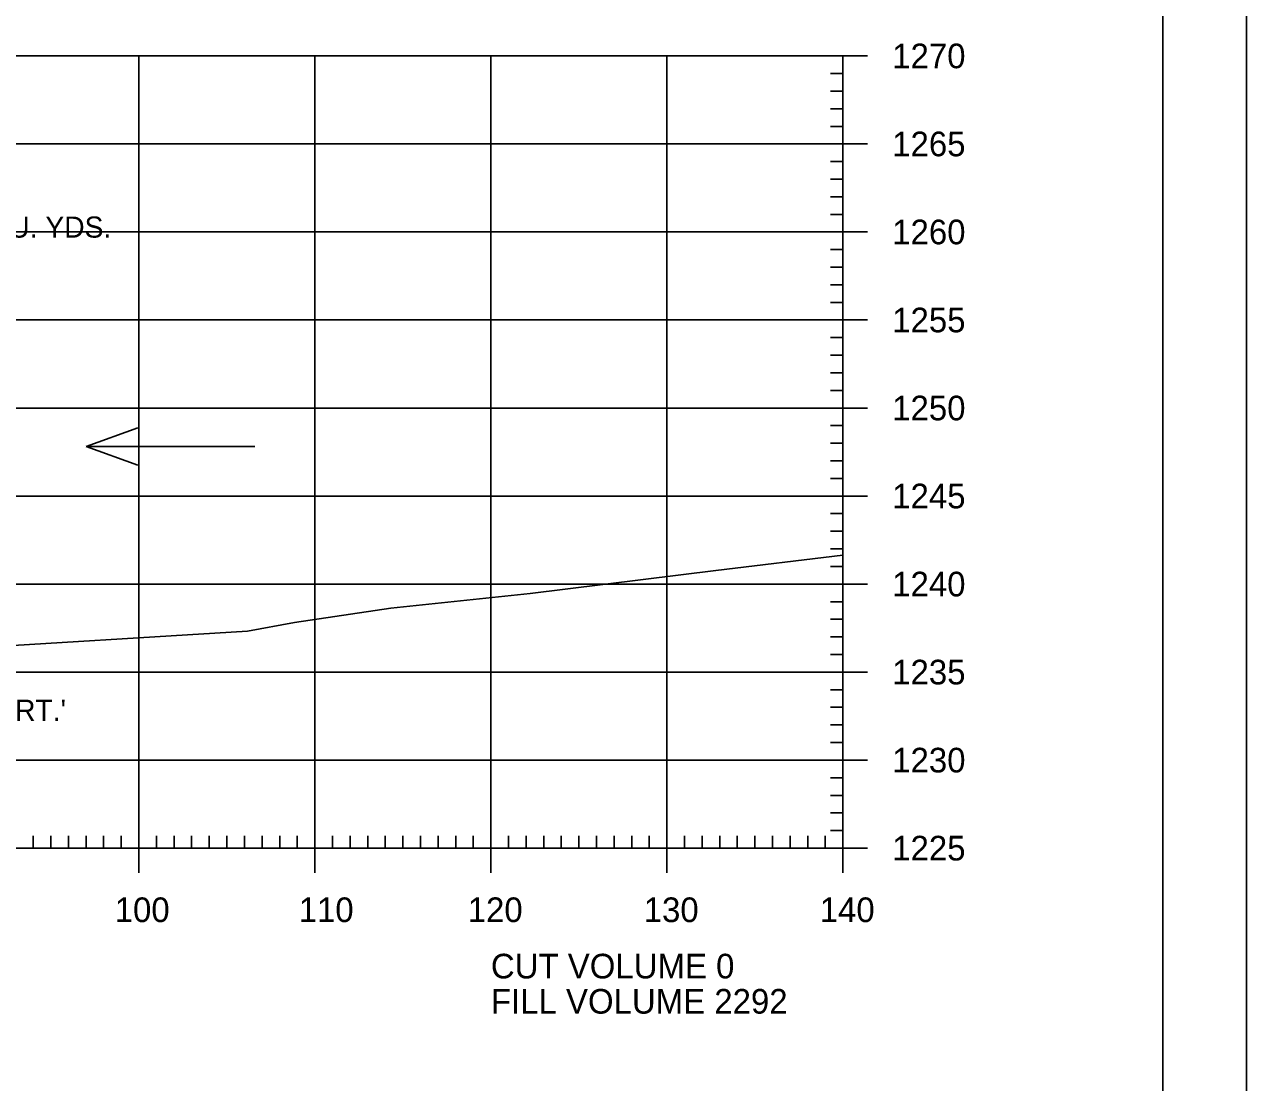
# Model space of a CAD drawing. Extents: x 1406028 to 1412453, y 321733 to 325986.
# Drawn here: x 1409148.3 to 1409217.7, y 321949.6 to 322009.7 of the extents above; entities that cross this region are included whole.
import ezdxf

# ---------------------------------------------------------------- set-up
doc = ezdxf.new("R2010")
doc.units = 0
for name, color, linetype in [('R_Axis', 7, 'Continuous'), ('R_Axis Annot', 7, 'Continuous'), ('R_Border', 7, 'Continuous'), ('R_Draft', 7, 'Continuous'), ('R_Exist Surface', 7, 'Continuous'), ('R_Grid', 7, 'Continuous'), ('R_Horz Alg Annot', 7, 'Continuous'), ('R_No Plot', 7, 'Continuous'), ('R_Water Annot', 7, 'Continuous')]:
    doc.layers.add(name, color=color, linetype=linetype)

msp = doc.modelspace()

# ---------------------------------------------------------------- linework, layer by layer
at = {"layer": 'R_Axis'}
for p, q in [((1409196.215, 322007.877), (1409193.415, 322007.877)), ((1409194.815, 321962.877), (1409194.815, 322007.877)), ((1409194.815, 322006.877), (1409194.115, 322006.877)), ((1409194.815, 322005.877), (1409194.115, 322005.877)), ((1409194.815, 322004.877), (1409194.115, 322004.877)), ((1409194.815, 322003.877), (1409194.115, 322003.877)), ((1409196.215, 322002.877), (1409193.415, 322002.877)), ((1409194.815, 322001.877), (1409194.115, 322001.877)), ((1409194.815, 322000.877), (1409194.115, 322000.877)), ((1409194.815, 321999.877), (1409194.115, 321999.877)), ((1409194.815, 321998.877), (1409194.115, 321998.877)), ((1409196.215, 321997.877), (1409193.415, 321997.877)), ((1409194.815, 321996.877), (1409194.115, 321996.877)), ((1409194.815, 321995.877), (1409194.115, 321995.877)), ((1409194.815, 321994.877), (1409194.115, 321994.877)), ((1409194.815, 321993.877), (1409194.115, 321993.877)), ((1409196.215, 321992.877), (1409193.415, 321992.877)), ((1409194.815, 321991.877), (1409194.115, 321991.877)), ((1409194.815, 321990.877), (1409194.115, 321990.877)), ((1409194.815, 321989.877), (1409194.115, 321989.877)), ((1409194.815, 321988.877), (1409194.115, 321988.877)), ((1409196.215, 321987.877), (1409193.415, 321987.877)), ((1409194.815, 321986.877), (1409194.115, 321986.877)), ((1409194.815, 321985.877), (1409194.115, 321985.877)), ((1409194.815, 321984.877), (1409194.115, 321984.877)), ((1409194.815, 321983.877), (1409194.115, 321983.877)), ((1409196.215, 321982.877), (1409193.415, 321982.877)), ((1409194.815, 321981.877), (1409194.115, 321981.877)), ((1409194.815, 321980.877), (1409194.115, 321980.877)), ((1409194.815, 321979.877), (1409194.115, 321979.877)), ((1409194.815, 321978.877), (1409194.115, 321978.877)), ((1409196.215, 321977.877), (1409193.415, 321977.877)), ((1409194.815, 321976.877), (1409194.115, 321976.877)), ((1409194.815, 321975.877), (1409194.115, 321975.877)), ((1409194.815, 321974.877), (1409194.115, 321974.877)), ((1409194.815, 321973.877), (1409194.115, 321973.877)), ((1409196.215, 321972.877), (1409193.415, 321972.877)), ((1409194.815, 321971.877), (1409194.115, 321971.877)), ((1409194.815, 321970.877), (1409194.115, 321970.877)), ((1409194.815, 321969.877), (1409194.115, 321969.877)), ((1409194.815, 321968.877), (1409194.115, 321968.877)), ((1409196.215, 321967.877), (1409193.415, 321967.877)), ((1409194.815, 321966.877), (1409194.115, 321966.877)), ((1409194.815, 321965.877), (1409194.115, 321965.877)), ((1409194.815, 321964.877), (1409194.115, 321964.877)), ((1409154.815, 321961.477), (1409154.815, 321964.277)), ((1409164.815, 321961.477), (1409164.815, 321964.277)), ((1409174.815, 321961.477), (1409174.815, 321964.277)), ((1409184.815, 321961.477), (1409184.815, 321964.277)), ((1409194.815, 321961.477), (1409194.815, 321964.277)), ((1409148.815, 321962.877), (1409148.815, 321963.577)), ((1409149.815, 321962.877), (1409149.815, 321963.577)), ((1409150.815, 321962.877), (1409150.815, 321963.577)), ((1409151.815, 321962.877), (1409151.815, 321963.577)), ((1409152.815, 321962.877), (1409152.815, 321963.577)), ((1409153.815, 321962.877), (1409153.815, 321963.577)), ((1409155.815, 321962.877), (1409155.815, 321963.577)), ((1409156.815, 321962.877), (1409156.815, 321963.577)), ((1409157.815, 321962.877), (1409157.815, 321963.577)), ((1409158.815, 321962.877), (1409158.815, 321963.577)), ((1409159.815, 321962.877), (1409159.815, 321963.577)), ((1409160.815, 321962.877), (1409160.815, 321963.577)), ((1409161.815, 321962.877), (1409161.815, 321963.577)), ((1409162.815, 321962.877), (1409162.815, 321963.577)), ((1409163.815, 321962.877), (1409163.815, 321963.577)), ((1409165.815, 321962.877), (1409165.815, 321963.577)), ((1409166.815, 321962.877), (1409166.815, 321963.577)), ((1409167.815, 321962.877), (1409167.815, 321963.577)), ((1409168.815, 321962.877), (1409168.815, 321963.577)), ((1409169.815, 321962.877), (1409169.815, 321963.577)), ((1409170.815, 321962.877), (1409170.815, 321963.577)), ((1409171.815, 321962.877), (1409171.815, 321963.577)), ((1409172.815, 321962.877), (1409172.815, 321963.577)), ((1409173.815, 321962.877), (1409173.815, 321963.577)), ((1409175.815, 321962.877), (1409175.815, 321963.577)), ((1409176.815, 321962.877), (1409176.815, 321963.577)), ((1409177.815, 321962.877), (1409177.815, 321963.577)), ((1409178.815, 321962.877), (1409178.815, 321963.577)), ((1409179.815, 321962.877), (1409179.815, 321963.577)), ((1409180.815, 321962.877), (1409180.815, 321963.577)), ((1409181.815, 321962.877), (1409181.815, 321963.577)), ((1409182.815, 321962.877), (1409182.815, 321963.577)), ((1409183.815, 321962.877), (1409183.815, 321963.577)), ((1409185.815, 321962.877), (1409185.815, 321963.577)), ((1409186.815, 321962.877), (1409186.815, 321963.577)), ((1409187.815, 321962.877), (1409187.815, 321963.577)), ((1409188.815, 321962.877), (1409188.815, 321963.577)), ((1409189.815, 321962.877), (1409189.815, 321963.577)), ((1409190.815, 321962.877), (1409190.815, 321963.577)), ((1409191.815, 321962.877), (1409191.815, 321963.577)), ((1409192.815, 321962.877), (1409192.815, 321963.577)), ((1409193.815, 321962.877), (1409193.815, 321963.577)), ((1409194.815, 321963.877), (1409194.115, 321963.877)), ((1408914.815, 321962.877), (1409194.815, 321962.877)), ((1409196.215, 321962.877), (1409193.415, 321962.877))]:
    msp.add_line(p, q, dxfattribs=at)
at = {"layer": 'R_Border'}
msp.add_line((1409212.995, 321846.877), (1409212.995, 322052.337), dxfattribs=at)
at = {"layer": 'R_Exist Surface'}
msp.add_lwpolyline([(1409073.222, 321972.485), (1409082.091, 321972.369), (1409092.828, 321972.247), (1409093.041, 321972.223), (1409098.394, 321971.718), (1409106.967, 321970.902), (1409107.271, 321970.881), (1409107.501, 321970.857), (1409121.823, 321972.904), (1409122.285, 321972.953), (1409133.015, 321973.452), (1409137.681, 321973.788), (1409144.241, 321974.185), (1409160.985, 321975.208), (1409163.653, 321975.692), (1409169.134, 321976.513), (1409177.046, 321977.346), (1409187.589, 321978.643), (1409194.815, 321979.521)], dxfattribs=at)
at = {"layer": 'R_Grid'}
for p, q in [((1408914.815, 322007.877), (1409194.815, 322007.877)), ((1409154.815, 321962.877), (1409154.815, 322007.877)), ((1409164.815, 321962.877), (1409164.815, 322007.877)), ((1409174.815, 321962.877), (1409174.815, 322007.877)), ((1409184.815, 321962.877), (1409184.815, 322007.877)), ((1409194.815, 321962.877), (1409194.815, 322007.877)), ((1408914.815, 322002.877), (1409194.815, 322002.877)), ((1408914.815, 321997.877), (1409194.815, 321997.877)), ((1408914.815, 321992.877), (1409194.815, 321992.877)), ((1408914.815, 321987.877), (1409194.815, 321987.877)), ((1408914.815, 321982.877), (1409194.815, 321982.877)), ((1408914.815, 321977.877), (1409194.815, 321977.877)), ((1408914.815, 321972.877), (1409194.815, 321972.877)), ((1408914.815, 321967.877), (1409194.815, 321967.877)), ((1408914.815, 321962.877), (1409194.815, 321962.877))]:
    msp.add_line(p, q, dxfattribs=at)
at = {"layer": 'R_No Plot'}
for points in [[(1408884.407, 322056.231), (1409217.747, 322056.231), (1409217.747, 321842.894), (1408884.407, 321842.894)], [(1409130.735, 322052.337), (1409150.355, 322052.337), (1409150.355, 322042.457), (1409166.467, 322042.457), (1409189.666, 322042.457), (1409189.666, 322018.124), (1409212.995, 322018.124), (1409212.995, 321846.877), (1408896.815, 321846.877), (1408896.815, 322052.337)]]:
    msp.add_lwpolyline(points, close=True, dxfattribs=at)
at = {"layer": 'R_Water Annot'}
for p, q in [((1409151.827, 321985.691), (1409154.756, 321986.757)), ((1409161.4, 321985.691), (1409151.827, 321985.691)), ((1409151.827, 321985.691), (1409154.756, 321984.625))]:
    msp.add_line(p, q, dxfattribs=at)

# ---------------------------------------------------------------- texts
at = {"layer": 'R_Axis Annot'}
for s, p in [('1270', (1409197.615, 322007.177)), ('1265', (1409197.615, 322002.177)), ('1260', (1409197.615, 321997.177)), ('1255', (1409197.615, 321992.177)), ('1250', (1409197.615, 321987.177)), ('1245', (1409197.615, 321982.177)), ('1240', (1409197.615, 321977.177)), ('1235', (1409197.615, 321972.177)), ('1230', (1409197.615, 321967.177)), ('1225', (1409197.615, 321962.177)), ('100', (1409153.442, 321958.677)), ('110', (1409163.894, 321958.677)), ('120', (1409173.497, 321958.677)), ('130', (1409183.497, 321958.677)), ('140', (1409193.497, 321958.677)), ('CUT VOLUME 0', (1409174.815, 321955.477)), ('FILL VOLUME 2292', (1409174.815, 321953.477))]:
    msp.add_text(s, height=1.4, dxfattribs=at).set_placement(p)
at = {"layer": 'R_Draft'}
msp.add_text('CONST. APPROACH ON LT. = 635 CU. YDS. ', height=1.2, dxfattribs=at).set_placement((1409120.211, 321997.555))
at = {"layer": 'R_Horz Alg Annot'}
msp.add_text("INLET = 1235.99 RT.'", height=1.2, dxfattribs=at).set_placement((1409135.162, 321970.108))

doc.saveas('drawing.dxf')
